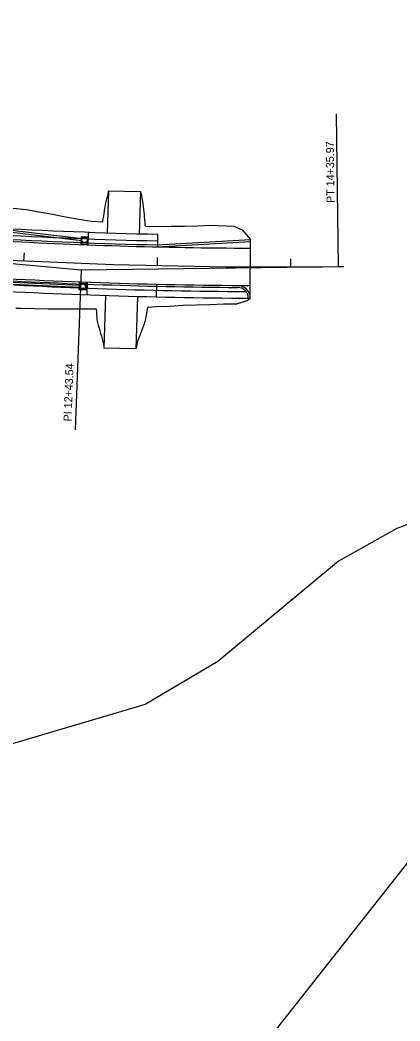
# Model space of a CAD drawing. Extents: x 979959 to 994833, y 1835619 to 1845316.
# Drawn here: x 992930 to 993215, y 1840093 to 1840844 of the extents above; entities that cross this region are included whole.
import ezdxf

# ---------------------------------------------------------------- set-up
doc = ezdxf.new("R2010")
doc.units = 0
for name, color, linetype in [('43', 7, 'Continuous'), ('R_Drainage', 7, 'Continuous'), ('R_Horz Alg', 7, 'Continuous'), ('R_Horz Alg Annot', 7, 'Continuous'), ('R_Horz Alg Annot_Side Road', 7, 'Continuous'), ('R_Horz Alg Stationing', 7, 'Continuous'), ('R_Proposed Const Limits', 7, 'Continuous'), ('R_Proposed Road', 7, 'Continuous')]:
    doc.layers.add(name, color=color, linetype=linetype)

msp = doc.modelspace()

# ---------------------------------------------------------------- linework, layer by layer
at = {"layer": '43'}
for points in [[(993019.26, 1839956.31), (993238.87, 1840234.94), (993402.97, 1840371.2), (993539.22, 1840518.3), (993603.66, 1840606.29), (993610.57, 1840641.48), (993651.95, 1840692.91), (993751.06, 1840806.72), (993965.69, 1841030.38), (994219.94, 1841293.78), (994360.04, 1841421.2), (994458.93, 1841499.01), (994563.94, 1841555.4), (994595.45, 1841599.5), (994648.23, 1841639.9), (994811.23, 1841773.79), (994833.11, 1841808.82)], [(993347.55, 1840512.83), (993212.6, 1840462.54), (993168.76, 1840438.22), (993078.36, 1840362.89), (993023.88, 1840330.57), (992872.5, 1840286.06), (992820.37, 1840265.31), (992785.96, 1840230.34), (992766.58, 1840187.1), (992757.72, 1840119.83), (992738.11, 1840069.09)]]:
    msp.add_lwpolyline(points, dxfattribs=at)
at = {"layer": 'R_Drainage'}
for p, q in [((992976.62, 1840678.32), (992867.24, 1840691.23)), ((992976.79, 1840679.81), (992867.41, 1840692.72)), ((992976.14, 1840681.44), (992981.14, 1840681.25)), ((992975.3, 1840643.21), (992863.87, 1840648.27)), ((992975.37, 1840644.71), (992863.94, 1840649.77)), ((992979.57, 1840641.26), (992974.57, 1840641.49))]:
    msp.add_line(p, q, dxfattribs=at)
for points in [[(992976.14, 1840681.44), (992981.14, 1840681.25), (992980.95, 1840676.26), (992975.95, 1840676.44)], [(992975.97, 1840676.94), (992980.97, 1840676.76), (992980.91, 1840675.26), (992975.92, 1840675.45)], [(992979.57, 1840641.26), (992974.57, 1840641.49), (992974.81, 1840646.49), (992979.8, 1840646.25)], [(992979.78, 1840645.75), (992974.78, 1840645.99), (992974.85, 1840647.48), (992979.85, 1840647.25)]]:
    msp.add_lwpolyline(points, close=True, dxfattribs=at)
for centre, radius in [((992978.55, 1840678.85), 2.5), ((992978.55, 1840678.85), 2.5), ((992978.55, 1840678.85), 2), ((992978.55, 1840678.85), 2), ((992977.19, 1840643.87), 2.5), ((992977.19, 1840643.87), 2.5), ((992977.19, 1840643.87), 2), ((992977.19, 1840643.87), 2)]:
    msp.add_circle(centre, radius, dxfattribs=at)
at = {"layer": 'R_Horz Alg'}
msp.add_line((993168.81, 1840658.97), (993172.84, 1840659.02), dxfattribs=at)
msp.add_arc((993121.27, 1844478.39), 3819.72, 264.93538, 270.7131, dxfattribs=at)
at = {"layer": 'R_Horz Alg Annot'}
msp.add_lwpolyline([(992976.07, 1840656.57), (992971.52, 1840536.65)], dxfattribs=at)
at = {"layer": 'R_Horz Alg Annot_Side Road'}
for p, q in [((992784.07, 1840673.58), (992976.07, 1840656.57)), ((992976.07, 1840656.57), (993168.81, 1840658.97))]:
    msp.add_line(p, q, dxfattribs=at)
msp.add_lwpolyline([(993168.81, 1840658.97), (993167.39, 1840773.36)], dxfattribs=at)
at = {"layer": 'R_Horz Alg Stationing'}
for points in [[(992933.22, 1840669.31), (992932.92, 1840663.32)], [(993032.99, 1840665.69), (993032.85, 1840659.69)], [(993132.83, 1840664.69), (993132.85, 1840658.69)]]:
    msp.add_lwpolyline(points, dxfattribs=at)
at = {"layer": 'R_Proposed Const Limits'}
for points in [[(992863.27, 1840724.09), (992866.71, 1840721.6), (992876.22, 1840715.94), (992885.84, 1840711.57), (992895.54, 1840708.19), (992905.3, 1840705.65), (992915.13, 1840704.3), (992924.96, 1840702.78), (992934.81, 1840701.59), (992944.65, 1840700.02), (992954.48, 1840698.12), (992964.32, 1840696.31), (992974.16, 1840694.51), (992984.03, 1840693), (992992.21, 1840692.41)], [(992992.21, 1840692.41), (992992.28, 1840692.83), (992992.58, 1840694.82), (992992.88, 1840696.82), (992993.19, 1840698.81), (992993.49, 1840700.8), (992993.79, 1840702.79), (992994.16, 1840704.78), (992994.57, 1840706.77), (992995.07, 1840708.76), (992995.59, 1840710.74), (992996.13, 1840712.73), (992996.52, 1840715.8)], [(993024.09, 1840689.12), (993024.03, 1840689.89), (993023.86, 1840691.89), (993023.69, 1840693.9), (993023.52, 1840695.91), (993023.35, 1840697.91), (993023.18, 1840699.92), (993023, 1840701.92), (993022.77, 1840703.93), (993022.49, 1840705.94), (993022.14, 1840707.95), (993021.79, 1840709.96), (993021.43, 1840711.97), (993021.17, 1840713.22), (993020.51, 1840715.08)], [(993024.09, 1840689.12), (993033.53, 1840688.96), (993043.46, 1840689.16), (993053.38, 1840689.11), (993063.31, 1840689.44), (993073.24, 1840689.95), (993090.45, 1840689.19), (993096.59, 1840686.54), (993102.95, 1840679.32)], [(993025.63, 1840628.58), (993032.14, 1840628.88), (993042.23, 1840629.32), (993052.32, 1840629.89), (993062.4, 1840630.16), (993072.49, 1840630.58), (993082.57, 1840630.92), (993092.64, 1840630.95), (993100.35, 1840633.49), (993102.73, 1840635.22)], [(992927.11, 1840627.82), (992931.17, 1840627.74), (992941.26, 1840627.5), (992951.35, 1840627.35), (992961.46, 1840627.36), (992971.55, 1840627.33), (992981.65, 1840627.24), (992987.3, 1840627.29)], [(993025.63, 1840628.58), (993024.93, 1840623.83), (993024.55, 1840621.84), (993024.13, 1840619.85), (993023.71, 1840617.87), (993023.09, 1840615.88), (993022.38, 1840613.9), (993021.65, 1840611.92), (993020.91, 1840609.94), (993020.18, 1840607.97), (993019.45, 1840605.99), (993018.72, 1840604.01), (993018.07, 1840602.03), (993017.66, 1840600.04), (993017.27, 1840598.05), (993016.97, 1840597.16)], [(992987.3, 1840627.29), (992987.4, 1840624.95), (992987.54, 1840622.94), (992987.67, 1840620.94), (992987.8, 1840618.93), (992988.24, 1840616.92), (992988.83, 1840614.9), (992989.42, 1840612.88), (992990.01, 1840610.86), (992990.6, 1840608.84), (992991.2, 1840606.83), (992991.79, 1840604.81), (992992.32, 1840602.79), (992992.65, 1840600.78), (992992.92, 1840598.77), (992992.98, 1840597.87)]]:
    msp.add_lwpolyline(points, dxfattribs=at)
at = {"layer": 'R_Proposed Road'}
for p, q in [((992996.52, 1840715.8), (992995.57, 1840684.25)), ((992996.52, 1840715.8), (993020.51, 1840715.08)), ((993020.51, 1840715.08), (993019.56, 1840683.53)), ((992981.23, 1840675.25), (992981.58, 1840684.74)), ((993033.34, 1840673.69), (993033.56, 1840683.18)), ((993033.09, 1840675.19), (993102.95, 1840679.32)), ((993033.18, 1840673.69), (993102.94, 1840677.82)), ((993102.73, 1840635.22), (993102.95, 1840679.32)), ((992980.46, 1840647.26), (992980.17, 1840637.76)), ((993032.43, 1840645.7), (993032.15, 1840636.2)), ((992994.16, 1840637.27), (992992.98, 1840597.87)), ((993018.15, 1840636.55), (993016.97, 1840597.16)), ((993016.97, 1840597.16), (992992.98, 1840597.87))]:
    msp.add_line(p, q, dxfattribs=at)
for centre, radius, start, end in [((993121.27, 1844478.39), 3796.22, 266.77491, 268.67602), ((993121.27, 1844478.39), 3804.22, 266.77491, 268.6736), ((993121.27, 1844478.39), 3801.22, 266.77491, 268.67602), ((993121.27, 1844478.39), 3805.72, 266.77491, 269.7236), ((993121.27, 1844478.39), 3835.22, 266.36298, 269.58197), ((993121.27, 1844478.39), 3833.72, 266.36298, 269.7236), ((993121.27, 1844478.39), 3843.22, 266.36298, 269.7236), ((993121.27, 1844478.39), 3838.22, 266.36298, 269.67514), ((993093.23, 1840635.27), 8, 359.7236, 89.58197), ((993093.23, 1840635.27), 9.5, 359.7236, 89.58197)]:
    msp.add_arc(centre, radius, start, end, dxfattribs=at)

# ---------------------------------------------------------------- texts
at = {"layer": 'R_Horz Alg Annot'}
msp.add_text('PI 12+43.54', height=6, rotation=87.82424, dxfattribs=at).set_placement((992968.75, 1840542.76))
at = {"layer": 'R_Horz Alg Annot_Side Road'}
msp.add_text('PT 14+35.97', height=6, rotation=90.7131, dxfattribs=at).set_placement((993165.89, 1840706.63))

doc.saveas('drawing.dxf')
